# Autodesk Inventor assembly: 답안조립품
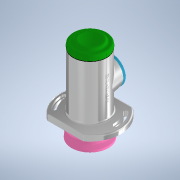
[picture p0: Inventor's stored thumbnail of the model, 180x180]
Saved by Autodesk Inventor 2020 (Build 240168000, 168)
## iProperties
Created: 2022-05
Part Number: 답안조립품
Document SubType Name: Assembly
Designer: Student
Author: Student
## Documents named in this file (22)
- C:\Users\Student\Desktop\720506V1020\답안조립품.iam
- C:\Users\Student\Desktop\720506V1020\본체.ipt
- C:\Users\Student\Desktop\720506V1020\베어링 6202.ipt
- C:\Users\Student\Desktop\720506V1020\탑 커버.ipt
- C:\Users\Student\Desktop\720506V1020\오일 실 15 x 30 x 7.ipt
- C:\Users\Student\Desktop\720506V1020\축.ipt
- C:\Users\Student\Desktop\720506V1020\부시1.ipt
- C:\Users\Student\Desktop\720506V1020\키 4 x 4.ipt
- C:\Users\Student\Desktop\720506V1020\V-벨트풀리.ipt
- C:\Users\Student\Desktop\720506V1020\와셔 4 x 16.ipt
- C:\Users\Student\Desktop\720506V1020\볼트 M4 x 10.ipt
- C:\Users\Student\Desktop\720506V1020\멈춤링 35 x 1.6.ipt
- C:\Users\Student\Desktop\720506V1020\부시2.ipt
- C:\Users\Student\Desktop\720506V1020\와셔 10 x 21.ipt
- C:\Users\Student\Desktop\720506V1020\너트 M10.ipt
- C:\Users\Student\Desktop\720506V1020\멈춤링 15 x 1.ipt
- C:\Users\Student\Desktop\720506V1020\개스킷.ipt
- C:\Users\Student\Desktop\720506V1020\사이드 커버.ipt
- 사이드 커버.ipt
- C:\Users\Student\Desktop\720506V1020\와셔 3 x 6.ipt
- C:\Users\Student\Desktop\720506V1020\십자볼트 M3 x 10.ipt
- C:\Users\Student\Desktop\720506V1020\멈춤나사 M3.ipt
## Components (3 placed, 3 different names)
1. V-벨트풀리:1
2. ISO 4017 M4 x 10:1
3. 개스킷:1
